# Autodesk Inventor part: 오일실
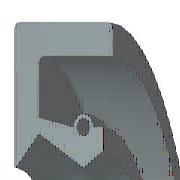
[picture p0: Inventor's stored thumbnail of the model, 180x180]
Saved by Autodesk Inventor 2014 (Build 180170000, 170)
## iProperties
Created: 2015-11
Part Number: 오일실
Material: 고무
Description: 오일-실
Document SubType Name: Modeling
Standard: KS B 2804
Designer: mdu
Standards Organization: KS
Language: ko-KR
Size Designation: D - 10 20 7
Categories: <MemberInstance><Categories><Category DisplayName="샤프트 부품" InternalName="7f7aeb1f-a693-4053-b835-cee3144e0d98" Mnemonic="SHFT"><Category DisplayName="실링" Intern
Density: 0.93 g/cm^3
Appearance: 고무 - 검은색 - 버전 1.1
Mass: 1.11329 g
Surface Area: 16.3871 cm^2
Volume: 1.19708 cm^3
IsCustomPart: 0
Author: mdu
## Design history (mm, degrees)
revolve "본체" stored, may be unused: angle "d17" = 90 deg
revolve "스프링1" stored, may be unused: angle "d18" = 90 deg
body "Solid1"
sketch "스케치1"
  geometry: L1 (0, 10)-(7, 10); L2 (7, 8.25)-(1.75, 8.25); L3 (1.75, 6.75)-(4.9, 5); L4 (4.9, 5)-(0, 5); L5 (0, 0)-(9.586, 0) reference; L6 (4.9, 5)-(6.3, 5.875); L7 (0, 18)-(0, -3) reference; L8 (-1.941, 0)-(11.507, 0) reference; L9 (4.2, 7.1)-(1.75, 7.59); L10 (1.75, 7.59)-(1.75, 8.25); L11 (0, 10)-(0, 5.088); L12 (4.9, 5)-(0, 5); L13 (1.75, 6.75)-(0.152, 5.028); L14 (7, 10)-(7, 8.25); L15 (5.6, 7.1)-(6.3, 7.1); L16 (6.3, 7.1)-(6.3, 5.875); C1 r 0.455 at (4.9, 7.1); A1 r 0.7 centre (4.9, 7.1) between (5.6, 7.1) and (4.2, 7.1); A2 r 0.088 centre (0.088, 5.088) between (0, 5.088) and (0.152, 5.028); 1 further point
  constraints: 28 end point, 5 horizontal alignment, 5 point on line, 4 point on circle, 4 vertical alignment, 3 centre point, 3 tangent, 2 collinear, 2 horizontal, 2 perpendicular, 1 coincident, 1 parallel
  dimensions: "d0" = 20 diameter of L1 L5 (= SD2); "d1" = 1.75 distance of L1.end L2.start (= SD); "d2" = 0.91 diameter of C1 (= SPDI); "d3" = 1.4 diameter of A1 (= SPDA); "d4" = 10 diameter of L3.end L5 (= NND); "d5" = 13.5 diameter of L3.start L5 (= TKDM); "d7" = 15.18 diameter of L9.end L5 (= TKDM + 0.24 x SWDT); "d8" = 1.75 distance between parallel lines of L11 L10 (= SD); "d9" = 4.9 distance from line of L11 C1.centre (= SPDST); "d10" = 14.2 diameter of C1.centre L5 (= HLDM); "d11" = 0.0875 radius of A2 (= 0.25 x LAB); "d12" = 6.3 distance between parallel lines of L11 L16 (= SDI); "d13" = 11.75 diameter of L6.end L5 (= ABDM); "d14" = 7 distance from line of L11 L1.end (= SWDT)
fillet "모깎기1" dims "d6" = 0.3 (= RR)
other parameters: "SD2" = 20 [user parameter; used in 1 equation term], "SWDT" = 7 [user parameter; used in 2 equation terms], "RR" = 0.3 [user parameter; used in 1 equation term], "SD" = 1.75 [user parameter; used in 2 equation terms], "NND" = 10 [user parameter; used in 1 equation term], "SPDA" = 1.4 [user parameter; used in 1 equation term], "SPDI" = 0.91 [user parameter; used in 1 equation term], "TKDM" = 13.5 [user parameter; used in 2 equation terms], "HLDM" = 14.2 [user parameter; used in 1 equation term], "ABDM" = 11.75 [user parameter; used in 1 equation term], "SDI" = 6.3 [user parameter; used in 1 equation term], "SPDST" = 4.9 [user parameter; used in 1 equation term], "LAB" = 0.35 [user parameter; used in 1 equation term], "d15" = 0, "d16" = 0, "d19" = 0
